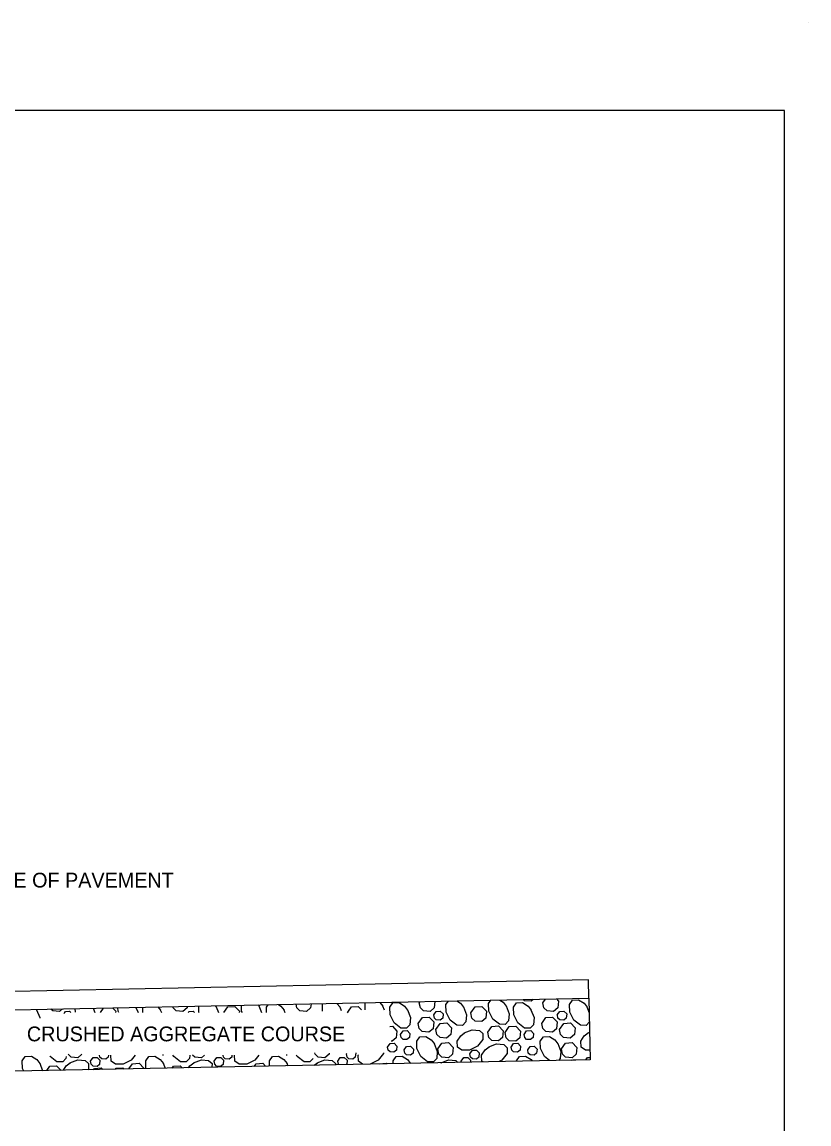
# Model space of a CAD drawing. Extents: x 49991.4 to 50021, y 49987.6 to 50011.4.
# Drawn here: x 50017.842 to 50021.038, y 50004.05 to 50008.524 of the extents above; entities that cross this region are included whole.
import ezdxf

# ---------------------------------------------------------------- set-up
doc = ezdxf.new("R2010")
doc.units = 0
doc.layers.add('Level 1', color=7, linetype='Continuous')
doc.layers.add('Level 2', color=7, linetype='Continuous')

msp = doc.modelspace()

# ---------------------------------------------------------------- linework, layer by layer
at = {"layer": 'Level 1'}
for p, q in [((50021.0378, 50008.5236), (50021.0378, 50008.5236)), ((50020.1431, 50004.6348), (50017.6426, 50004.5848)), ((50020.1446, 50004.5599), (50020.1431, 50004.6348)), ((50017.132, 50004.4997), (50020.1446, 50004.5599)), ((50020.1446, 50004.5599), (50020.1496, 50004.3104)), ((50020.1496, 50004.3104), (50015.4298, 50004.216))]:
    msp.add_line(p, q, dxfattribs=at)
msp.add_lwpolyline([(50020.9378, 50008.1646), (50009.7374, 50008.1646), (50009.7374, 49999.8856), (50020.9378, 49999.8856)], close=True, dxfattribs=at)
for points in [[(50019.0626, 50004.5074), (50019.0621, 50004.5349), (50019.0645, 50004.5383)], [(50019.1211, 50004.5395), (50019.1337, 50004.5237)], [(50019.2358, 50004.5125), (50019.2353, 50004.5391), (50019.2373, 50004.5418)], [(50019.2949, 50004.543), (50019.3069, 50004.5279)], [(50019.4072, 50004.5137), (50019.4198, 50004.4818), (50019.4173, 50004.4525), (50019.4041, 50004.4386), (50019.3803, 50004.439), (50019.3533, 50004.4601), (50019.337, 50004.4928), (50019.3364, 50004.5236), (50019.3487, 50004.5409), (50019.3732, 50004.5426), (50019.3952, 50004.5285), (50019.408, 50004.5124)], [(50019.5188, 50004.5474), (50019.5161, 50004.5208), (50019.4993, 50004.5069), (50019.4724, 50004.5088), (50019.4598, 50004.5211), (50019.4557, 50004.5421)], [(50019.4557, 50004.5421), (50019.4585, 50004.5462)], [(50019.6346, 50004.525), (50019.6473, 50004.4931), (50019.6448, 50004.4638), (50019.6315, 50004.4499), (50019.6077, 50004.4504), (50019.5807, 50004.4715), (50019.5644, 50004.5041), (50019.5639, 50004.5349), (50019.5735, 50004.5485)], [(50019.608, 50004.5492), (50019.6226, 50004.5398), (50019.6355, 50004.5237)], [(50019.8079, 50004.5292), (50019.8206, 50004.4973), (50019.818, 50004.468), (50019.8048, 50004.454), (50019.781, 50004.4545), (50019.754, 50004.4756), (50019.7377, 50004.5083), (50019.7371, 50004.5391), (50019.7463, 50004.552)], [(50019.7823, 50004.5527), (50019.7959, 50004.544), (50019.8087, 50004.5279)], [(50019.909, 50004.5137), (50019.9216, 50004.4818), (50019.9191, 50004.4525), (50019.9059, 50004.4386), (50019.8821, 50004.439), (50019.8551, 50004.4601), (50019.8388, 50004.4928), (50019.8382, 50004.5236), (50019.8505, 50004.5409), (50019.875, 50004.5426), (50019.897, 50004.5285), (50019.9098, 50004.5124)], [(50019.9181, 50004.5554), (50019.9093, 50004.5481), (50019.8824, 50004.55), (50019.8777, 50004.5546)], [(50020.012, 50004.5573), (50020.0207, 50004.5483), (50020.0179, 50004.5208), (50020.0011, 50004.5069), (50019.9742, 50004.5088), (50019.9616, 50004.5211), (50019.9575, 50004.5421)], [(50019.9575, 50004.5421), (50019.9675, 50004.5564)], [(50020.1465, 50004.4638), (50020.1333, 50004.4499), (50020.1095, 50004.4504), (50020.0825, 50004.4715), (50020.0662, 50004.5041), (50020.0656, 50004.5349), (50020.078, 50004.5523), (50020.1025, 50004.5539), (50020.1244, 50004.5398), (50020.1372, 50004.5237)], [(50017.9005, 50004.5151), (50017.9027, 50004.5124)], [(50017.9018, 50004.5137), (50017.9145, 50004.4818), (50017.9142, 50004.479)], [(50018.0064, 50004.5172), (50017.994, 50004.5069), (50017.9671, 50004.5088), (50017.9594, 50004.5162)], [(50018.0127, 50004.4979), (50018.0161, 50004.5027)], [(50018.0161, 50004.5027), (50018.0191, 50004.507), (50018.0355, 50004.508), (50018.0411, 50004.5021)], [(50018.059, 50004.5041), (50018.0588, 50004.5182)], [(50018.1314, 50004.5197), (50018.1385, 50004.5018)], [(50018.1605, 50004.5018), (50018.1737, 50004.5205)], [(50018.2094, 50004.5212), (50018.2231, 50004.5071), (50018.2226, 50004.5018)], [(50018.2356, 50004.5018), (50018.2323, 50004.5083), (50018.2321, 50004.5217)], [(50018.3049, 50004.5232), (50018.3134, 50004.5018)], [(50018.3332, 50004.5018), (50018.3329, 50004.5236), (50018.3329, 50004.5237)], [(50018.3944, 50004.5249), (50018.4045, 50004.5124)], [(50018.4036, 50004.5137), (50018.4084, 50004.5018)], [(50018.5132, 50004.5273), (50018.5126, 50004.5208), (50018.4957, 50004.5069), (50018.4689, 50004.5088), (50018.4562, 50004.5211), (50018.4552, 50004.5262)], [(50018.5172, 50004.5018), (50018.5209, 50004.507), (50018.5372, 50004.508), (50018.5432, 50004.5018)], [(50018.562, 50004.5018), (50018.5608, 50004.5041), (50018.5604, 50004.5283)], [(50018.6272, 50004.5296), (50018.6319, 50004.5237)], [(50018.6311, 50004.525), (50018.6403, 50004.5018)], [(50018.6623, 50004.5018), (50018.6787, 50004.5252), (50018.706, 50004.5267), (50018.7249, 50004.5071), (50018.7244, 50004.5018)], [(50018.7374, 50004.5018), (50018.7341, 50004.5083), (50018.7337, 50004.5317)], [(50018.801, 50004.5331), (50018.8052, 50004.5279)], [(50018.8043, 50004.5292), (50018.8152, 50004.5018)], [(50018.835, 50004.5018), (50018.8346, 50004.5236), (50018.842, 50004.5339)], [(50018.8837, 50004.5347), (50018.8934, 50004.5285), (50018.9062, 50004.5124)], [(50018.9054, 50004.5137), (50018.9101, 50004.5018)], [(50019.016, 50004.5374), (50019.0143, 50004.5208), (50018.9975, 50004.5069), (50018.9707, 50004.5088), (50018.958, 50004.5211), (50018.9551, 50004.5362)], [(50019.1329, 50004.525), (50019.1384, 50004.5109)], [(50019.1635, 50004.5009), (50019.1684, 50004.5078)], [(50019.1684, 50004.5078), (50019.1805, 50004.5252), (50019.2077, 50004.5267), (50019.2207, 50004.5133)], [(50019.3061, 50004.5292), (50019.3125, 50004.5132)], [(50019.5143, 50004.4925), (50019.5245, 50004.507), (50019.5408, 50004.508), (50019.5522, 50004.4962), (50019.5505, 50004.4797), (50019.5404, 50004.4713), (50019.5243, 50004.4725), (50019.5167, 50004.4798), (50019.5143, 50004.4925)], [(50019.6653, 50004.5009), (50019.6823, 50004.5252), (50019.7095, 50004.5267), (50019.7285, 50004.5071), (50019.7257, 50004.4796), (50019.7089, 50004.4656), (50019.682, 50004.4676), (50019.6694, 50004.4798), (50019.6653, 50004.5009)], [(50020.016, 50004.4925), (50020.0263, 50004.507), (50020.0426, 50004.508), (50020.054, 50004.4962), (50020.0523, 50004.4797), (50020.0422, 50004.4713), (50020.0261, 50004.4725), (50020.0185, 50004.4798), (50020.0161, 50004.4925)], [(50020.1364, 50004.525), (50020.1458, 50004.5015)], [(50019.4509, 50004.4579), (50019.4679, 50004.4822), (50019.4952, 50004.4837), (50019.5141, 50004.4641), (50019.5114, 50004.4366), (50019.4945, 50004.4226), (50019.4677, 50004.4246), (50019.455, 50004.4369), (50019.4509, 50004.4579)], [(50019.5229, 50004.4339), (50019.54, 50004.4581), (50019.5672, 50004.4597), (50019.5861, 50004.4401), (50019.5834, 50004.4125), (50019.5666, 50004.3986), (50019.5397, 50004.4005), (50019.5271, 50004.4128), (50019.523, 50004.4339)], [(50019.9527, 50004.4579), (50019.9697, 50004.4822), (50019.997, 50004.4837), (50020.0159, 50004.4641), (50020.0131, 50004.4366), (50019.9963, 50004.4226), (50019.9694, 50004.4246), (50019.9568, 50004.4369), (50019.9527, 50004.4579)], [(50020.0247, 50004.4339), (50020.0418, 50004.4581), (50020.069, 50004.4597), (50020.0879, 50004.4401), (50020.0852, 50004.4125), (50020.0684, 50004.3986), (50020.0415, 50004.4005), (50020.0288, 50004.4128), (50020.0247, 50004.4339)], [(50019.3365, 50004.4461), (50019.3461, 50004.4466), (50019.365, 50004.427), (50019.3623, 50004.3995), (50019.3455, 50004.3855), (50019.3419, 50004.3858)], [(50019.3794, 50004.4133), (50019.3896, 50004.4279), (50019.406, 50004.4288), (50019.4173, 50004.417), (50019.4157, 50004.4005), (50019.4056, 50004.3921), (50019.3895, 50004.3933), (50019.3819, 50004.4007), (50019.3794, 50004.4133)], [(50019.516, 50004.3765), (50019.5287, 50004.3446), (50019.5261, 50004.3153), (50019.5129, 50004.3014), (50019.4891, 50004.3018), (50019.4621, 50004.323), (50019.4458, 50004.3556), (50019.4453, 50004.3864), (50019.4576, 50004.4037), (50019.4821, 50004.4054), (50019.504, 50004.3913), (50019.5169, 50004.3752)], [(50019.6384, 50004.4196), (50019.6703, 50004.4323), (50019.6996, 50004.4297), (50019.7135, 50004.4165), (50019.7131, 50004.3927), (50019.6919, 50004.3657), (50019.6593, 50004.3494), (50019.6285, 50004.3488), (50019.6112, 50004.3611), (50019.6095, 50004.3857), (50019.6236, 50004.4076), (50019.6397, 50004.4204)], [(50019.7335, 50004.4218), (50019.7505, 50004.4461), (50019.7778, 50004.4476), (50019.7967, 50004.428), (50019.7939, 50004.4005), (50019.7771, 50004.3866), (50019.7503, 50004.3885), (50019.7376, 50004.4008), (50019.7335, 50004.4218)], [(50019.8036, 50004.4208), (50019.8207, 50004.4451), (50019.8479, 50004.4466), (50019.8668, 50004.427), (50019.8641, 50004.3995), (50019.8473, 50004.3855), (50019.8204, 50004.3875), (50019.8078, 50004.3997), (50019.8036, 50004.4208)], [(50019.8812, 50004.4133), (50019.8914, 50004.4279), (50019.9078, 50004.4288), (50019.9191, 50004.417), (50019.9175, 50004.4005), (50019.9074, 50004.3921), (50019.8913, 50004.3933), (50019.8837, 50004.4007), (50019.8812, 50004.4133)], [(50019.9842, 50004.3071), (50019.9639, 50004.323), (50019.9476, 50004.3556), (50019.947, 50004.3864), (50019.9593, 50004.4037), (50019.9839, 50004.4054), (50020.0058, 50004.3913), (50020.0186, 50004.3752)], [(50020.1488, 50004.3492), (50020.1303, 50004.3488), (50020.113, 50004.3611), (50020.1113, 50004.3857), (50020.1254, 50004.4076), (50020.1415, 50004.4204)], [(50020.1402, 50004.4196), (50020.1473, 50004.4225)], [(50019.3266, 50004.3621), (50019.3369, 50004.3767), (50019.3532, 50004.3776), (50019.3646, 50004.3659), (50019.3629, 50004.3494), (50019.3528, 50004.341), (50019.3367, 50004.3422), (50019.3291, 50004.3495), (50019.3267, 50004.3621)], [(50019.3938, 50004.3502), (50019.404, 50004.3647), (50019.4204, 50004.3656), (50019.4317, 50004.3539), (50019.4301, 50004.3374), (50019.42, 50004.329), (50019.4039, 50004.3302), (50019.3963, 50004.3375), (50019.3938, 50004.3502)], [(50019.5305, 50004.3541), (50019.5476, 50004.3783), (50019.5748, 50004.3799), (50019.5937, 50004.3603), (50019.591, 50004.3328), (50019.5742, 50004.3188), (50019.5473, 50004.3207), (50019.5346, 50004.333), (50019.5305, 50004.3541)], [(50019.7136, 50004.3017), (50019.7101, 50004.3042), (50019.7085, 50004.3287), (50019.7225, 50004.3506), (50019.7386, 50004.3635)], [(50019.7373, 50004.3627), (50019.7692, 50004.3753), (50019.7985, 50004.3728), (50019.8125, 50004.3595), (50019.812, 50004.3357), (50019.7909, 50004.3087), (50019.7794, 50004.303)], [(50019.8284, 50004.3621), (50019.8387, 50004.3767), (50019.855, 50004.3776), (50019.8663, 50004.3659), (50019.8647, 50004.3494), (50019.8546, 50004.341), (50019.8385, 50004.3422), (50019.8309, 50004.3495), (50019.8284, 50004.3621)], [(50019.8956, 50004.3502), (50019.9058, 50004.3647), (50019.9221, 50004.3656), (50019.9335, 50004.3539), (50019.9319, 50004.3374), (50019.9218, 50004.329), (50019.9057, 50004.3302), (50019.8981, 50004.3375), (50019.8956, 50004.3502)], [(50020.0178, 50004.3765), (50020.0305, 50004.3446), (50020.0279, 50004.3153), (50020.0208, 50004.3078)], [(50020.0323, 50004.3541), (50020.0494, 50004.3783), (50020.0766, 50004.3799), (50020.0955, 50004.3603), (50020.0928, 50004.3328), (50020.076, 50004.3188), (50020.0491, 50004.3207), (50020.0364, 50004.333), (50020.0323, 50004.3541)], [(50017.8494, 50004.2644), (50017.844, 50004.2752), (50017.8434, 50004.306), (50017.8557, 50004.3233), (50017.8803, 50004.3249), (50017.9022, 50004.3109), (50017.915, 50004.2948)], [(50018.0215, 50004.3231), (50018.0208, 50004.3153), (50018.0076, 50004.3014), (50017.9838, 50004.3018), (50017.9568, 50004.323), (50017.9558, 50004.3249)], [(50018.0856, 50004.3328), (50018.0688, 50004.3188), (50018.0419, 50004.3207), (50018.0293, 50004.333)], [(50018.1208, 50004.3046), (50018.1311, 50004.3192), (50018.1474, 50004.3201), (50018.1587, 50004.3083), (50018.1571, 50004.2918), (50018.147, 50004.2834), (50018.1309, 50004.2846), (50018.1233, 50004.2919), (50018.1208, 50004.3046)], [(50018.193, 50004.3292), (50018.1923, 50004.3214), (50018.1822, 50004.313), (50018.166, 50004.3142), (50018.1585, 50004.3215), (50018.157, 50004.3292)], [(50018.3016, 50004.3292), (50018.2855, 50004.3087), (50018.2529, 50004.2924), (50018.2221, 50004.2919), (50018.2048, 50004.3042), (50018.2031, 50004.3287), (50018.2035, 50004.3292)], [(50018.3462, 50004.2743), (50018.3458, 50004.2752), (50018.3452, 50004.306), (50018.3575, 50004.3233), (50018.382, 50004.3249), (50018.404, 50004.3109), (50018.4168, 50004.2948)], [(50018.4167, 50004.3292), (50018.4164, 50004.329), (50018.413, 50004.3292)], [(50018.5238, 50004.3292), (50018.5226, 50004.3153), (50018.5093, 50004.3014), (50018.4856, 50004.3018), (50018.4585, 50004.323), (50018.4554, 50004.3292)], [(50018.5832, 50004.3292), (50018.5706, 50004.3188), (50018.5437, 50004.3207), (50018.5349, 50004.3292)], [(50018.6226, 50004.3046), (50018.6328, 50004.3192), (50018.6492, 50004.3201), (50018.6605, 50004.3083), (50018.6589, 50004.2918), (50018.6488, 50004.2834), (50018.6327, 50004.2846), (50018.6251, 50004.2919), (50018.6226, 50004.3046)], [(50018.6948, 50004.3292), (50018.6941, 50004.3214), (50018.684, 50004.313), (50018.6678, 50004.3142), (50018.6603, 50004.3215), (50018.6588, 50004.3292)], [(50018.8034, 50004.3292), (50018.7873, 50004.3087), (50018.7547, 50004.2924), (50018.7239, 50004.2919), (50018.7065, 50004.3042), (50018.7049, 50004.3287), (50018.7053, 50004.3292)], [(50018.8474, 50004.2844), (50018.847, 50004.306), (50018.8593, 50004.3233), (50018.8838, 50004.3249), (50018.9058, 50004.3109), (50018.9186, 50004.2948)], [(50018.9185, 50004.3292), (50018.9182, 50004.329), (50018.9148, 50004.3292)], [(50019.0244, 50004.3153), (50019.0111, 50004.3014), (50018.9874, 50004.3018), (50018.9603, 50004.323), (50018.9572, 50004.3292)], [(50019.0896, 50004.3373), (50019.0892, 50004.3328), (50019.0724, 50004.3188), (50019.0455, 50004.3207), (50019.0329, 50004.333), (50019.0319, 50004.3379)], [(50019.1244, 50004.3046), (50019.1346, 50004.3192), (50019.151, 50004.3201), (50019.1623, 50004.3083), (50019.1607, 50004.2918), (50019.1592, 50004.2906)], [(50019.1975, 50004.3379), (50019.1958, 50004.3214), (50019.1857, 50004.313), (50019.1696, 50004.3142), (50019.162, 50004.3215), (50019.1596, 50004.3342)], [(50019.1596, 50004.3342), (50019.1617, 50004.3372)], [(50019.2256, 50004.2919), (50019.2083, 50004.3042), (50019.2067, 50004.3287), (50019.2081, 50004.3308)], [(50019.3103, 50004.3389), (50019.3102, 50004.3357), (50019.2891, 50004.3087), (50019.2567, 50004.2925)], [(50019.349, 50004.2944), (50019.3488, 50004.306), (50019.3611, 50004.3233), (50019.3856, 50004.3249), (50019.4075, 50004.3109), (50019.4196, 50004.2958)], [(50019.6262, 50004.3046), (50019.6364, 50004.3192), (50019.6527, 50004.3201), (50019.6641, 50004.3083), (50019.6633, 50004.3007)], [(50019.6614, 50004.3342), (50019.6716, 50004.3487), (50019.6879, 50004.3497), (50019.6993, 50004.3379), (50019.6976, 50004.3214), (50019.6875, 50004.313), (50019.6714, 50004.3142), (50019.6638, 50004.3215), (50019.6614, 50004.3342)], [(50019.8506, 50004.3044), (50019.8506, 50004.306), (50019.8629, 50004.3233), (50019.8874, 50004.3249), (50019.9093, 50004.3109), (50019.9135, 50004.3057)], [(50020.1318, 50004.31), (50020.1382, 50004.3192), (50020.1494, 50004.3198)], [(50017.9142, 50004.2961), (50017.9262, 50004.2659)], [(50017.943, 50004.2663), (50017.9558, 50004.2845), (50017.983, 50004.2861), (50018.001, 50004.2674)], [(50018.0107, 50004.2676), (50018.0223, 50004.2857), (50018.0384, 50004.2985)], [(50018.0371, 50004.2977), (50018.069, 50004.3103), (50018.0983, 50004.3078), (50018.1122, 50004.2946), (50018.1118, 50004.2708), (50018.1109, 50004.2696)], [(50018.1329, 50004.2701), (50018.1367, 50004.2755), (50018.164, 50004.2771), (50018.17, 50004.2708)], [(50018.2214, 50004.2718), (50018.2247, 50004.2765), (50018.2519, 50004.2781), (50018.2573, 50004.2725)], [(50018.2758, 50004.2729), (50018.2908, 50004.2943), (50018.318, 50004.2959), (50018.337, 50004.2763), (50018.3367, 50004.2741)], [(50018.416, 50004.2961), (50018.424, 50004.2759)], [(50018.4519, 50004.2764), (50018.4576, 50004.2845), (50018.4848, 50004.2861), (50018.4933, 50004.2773)], [(50018.519, 50004.2778), (50018.5241, 50004.2857), (50018.5402, 50004.2985)], [(50018.5389, 50004.2977), (50018.5708, 50004.3103), (50018.6001, 50004.3078), (50018.614, 50004.2946), (50018.6137, 50004.2797)], [(50018.7847, 50004.2831), (50018.7926, 50004.2943), (50018.8198, 50004.2959), (50018.8313, 50004.284)], [(50018.9178, 50004.2961), (50018.9218, 50004.2858)], [(50019.0288, 50004.288), (50019.0419, 50004.2985)], [(50019.0407, 50004.2977), (50019.0726, 50004.3103), (50019.1018, 50004.3078), (50019.1158, 50004.2946), (50019.1157, 50004.2897)], [(50019.1289, 50004.29), (50019.1269, 50004.2919), (50019.1244, 50004.3046)], [(50019.2936, 50004.2933), (50019.2944, 50004.2943), (50019.3216, 50004.2959), (50019.3235, 50004.2939)], [(50019.4196, 50004.2961), (50019.4197, 50004.2958)], [(50019.5435, 50004.2983), (50019.5437, 50004.2985)], [(50019.544, 50004.2983), (50019.5743, 50004.3103), (50019.6036, 50004.3078), (50019.6122, 50004.2996)], [(50019.6271, 50004.2999), (50019.6262, 50004.3046)], [(50020.0724, 50004.3089), (50020.0761, 50004.3103), (50020.0893, 50004.3092)]]:
    msp.add_lwpolyline(points, dxfattribs=at)

# ---------------------------------------------------------------- texts
at = {"layer": 'Level 2'}
for s, p in [('EDGE OF PAVEMENT', (50017.6338, 50005.0097)), ('CRUSHED AGGREGATE COURSE', (50017.8622, 50004.3853))]:
    msp.add_text(s, height=0.06, dxfattribs=at).set_placement(p)

doc.saveas('drawing.dxf')
